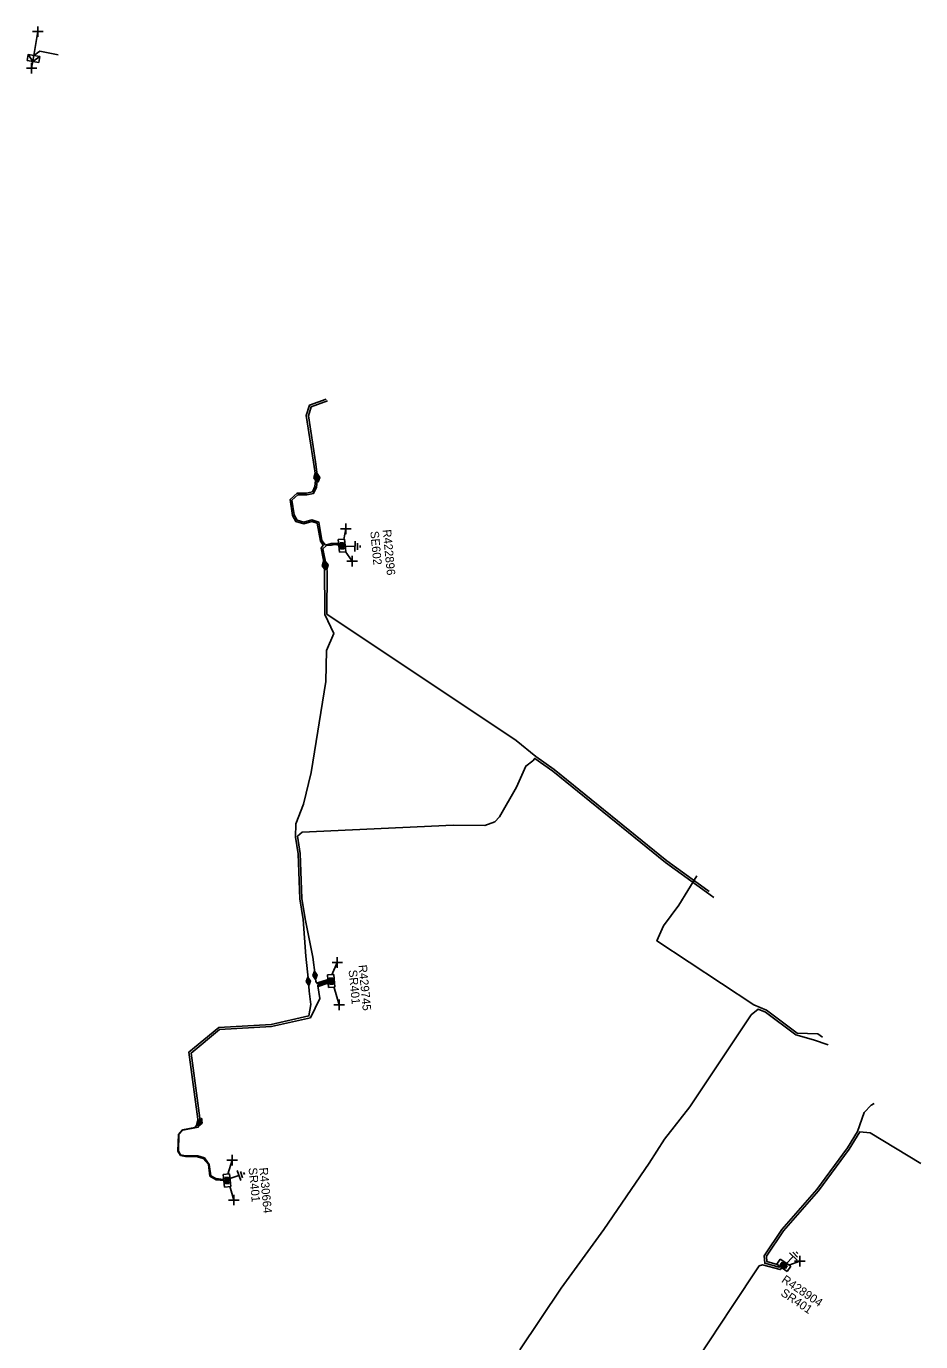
# Model space of a CAD drawing. Extents: x -540247 to -537390, y -1183887 to -1180355.
# Drawn here: x -538959.8 to -538854.3, y -1181292.1 to -1181136.9 of the extents above; entities that cross this region are included whole.
import ezdxf

# ---------------------------------------------------------------- set-up
doc = ezdxf.new("R2010")
doc.units = 0
for name, color, linetype in [('Vrstva 1', 7, 'Continuous'), ('Vrstva 14', 7, 'Continuous'), ('Vrstva 15', 7, 'Continuous'), ('Vrstva 19', 7, 'Continuous'), ('Vrstva 20', 7, 'Continuous'), ('Vrstva 28', 7, 'Continuous'), ('Vrstva 29', 7, 'Continuous'), ('Vrstva 30', 7, 'Continuous'), ('Vrstva 31', 7, 'Continuous'), ('Vrstva 34', 7, 'Continuous'), ('Vrstva 4', 7, 'Continuous'), ('Vrstva 5', 7, 'Continuous'), ('Vrstva 52', 7, 'Continuous'), ('Vrstva 59', 7, 'Continuous'), ('Vrstva 8', 7, 'Continuous'), ('Vrstva 9', 7, 'Continuous')]:
    doc.layers.add(name, color=color, linetype=linetype)

# ---------------------------------------------------------------- blocks, each defined once
blk = doc.blocks.new('NN870')
at = {"layer": 'Vrstva 4'}
for points in [[(0, -0.25), (0.5, 0), (0, 0.25), (-0.5, 0), (0, -0.25)], [(0.37, 0), (0, 0.19), (-0.36, 0), (0, -0.19), (0.37, 0)], [(0.24, 0), (0, 0.12), (-0.25, 0), (0, -0.12), (0.24, 0)], [(0.12, 0), (0, 0.06), (-0.13, 0), (0, -0.06), (0.12, 0)]]:
    blk.add_lwpolyline(points, dxfattribs=at)
blk = doc.blocks.new('NN800')
at = {"layer": 'Vrstva 1'}
for points in [[(-0.44, 0.44), (0.44, -0.44)], [(-0.44, -0.44), (0.44, 0.44)]]:
    blk.add_lwpolyline(points, dxfattribs=at)
blk = doc.blocks.new('NN620')
at = {"layer": 'Vrstva 8'}
for points in [[(0.75, 0), (-0.75, 0)], [(-0.75, 0), (-0.75, -0.75)], [(0.75, -0.75), (0.75, 0)], [(-0.75, -0.75), (0.75, -0.75)], [(0.37, -0.18), (-0.38, -0.18)], [(-0.38, -0.18), (-0.38, -0.56)], [(-0.38, -0.56), (0.37, -0.56)], [(0.32, -0.23), (-0.33, -0.23)], [(-0.33, -0.23), (-0.33, -0.51)], [(-0.33, -0.51), (0.32, -0.51)], [(0.27, -0.27), (-0.28, -0.27)], [(-0.28, -0.27), (-0.28, -0.46)], [(-0.28, -0.46), (0.27, -0.46)], [(0.23, -0.32), (-0.23, -0.32)], [(-0.23, -0.32), (-0.23, -0.42)], [(-0.23, -0.42), (0.23, -0.42)], [(-0.19, -0.37), (0.19, -0.37)], [(0.23, -0.42), (0.23, -0.32)], [(0.27, -0.46), (0.27, -0.27)], [(0.32, -0.51), (0.32, -0.23)], [(0.37, -0.56), (0.37, -0.18)]]:
    blk.add_lwpolyline(points, dxfattribs=at)
blk = doc.blocks.new('NN630')
at = {"layer": 'Vrstva 9'}
for points in [[(0, -0.7), (-0.7, 0)], [(-0.7, -0.7), (-0.7, 0), (0.7, 0), (0.7, -0.7)], [(-0.7, -0.7), (0.7, -0.7)], [(0, -0.7), (0.7, 0)]]:
    blk.add_lwpolyline(points, dxfattribs=at)
blk = doc.blocks.new('NN810')
at = {"layer": 'Vrstva 14'}
for points in [[(0, -0.64), (0, -1.89)], [(0.63, -1.89), (-0.62, -1.89)], [(0.39, -2.2), (-0.4, -2.2)], [(0, -2.52), (-0.12, -2.52)], [(0.14, -2.52), (0, -2.52)]]:
    blk.add_lwpolyline(points, dxfattribs=at)

msp = doc.modelspace()

# ---------------------------------------------------------------- linework, layer by layer
at = {"layer": 'Vrstva 20'}
for points in [[(-538924.3, -1181249.38), (-538924.25, -1181249.52), (-538925.39, -1181249.92), (-538925.44, -1181249.77)], [(-538924.28, -1181249.65), (-538924.23, -1181249.79), (-538925.37, -1181250.18), (-538925.42, -1181250.03)]]:
    msp.add_lwpolyline(points, close=True, dxfattribs=at)
at = {"layer": 'Vrstva 5'}
for points in [[(-538925.64, -1181190.12), (-538925.92, -1181188.3), (-538926.79, -1181182.81), (-538926.41, -1181181.59), (-538924.44, -1181180.87)], [(-538925.44, -1181190.14), (-538925.68, -1181188.26), (-538926.53, -1181182.83), (-538926.21, -1181181.79), (-538924.28, -1181181.08)], [(-538924.64, -1181200.51), (-538925.04, -1181198.47), (-538924.78, -1181198.1), (-538925.12, -1181197.63), (-538925.49, -1181195.53), (-538926.13, -1181195.32), (-538927.07, -1181195.59), (-538928, -1181195.33), (-538928.39, -1181194.6), (-538928.68, -1181192.72), (-538927.87, -1181191.97), (-538926.74, -1181191.97), (-538926.05, -1181191.83), (-538925.76, -1181191.2), (-538925.64, -1181190.12)], [(-538922.95, -1181197.92), (-538923.84, -1181197.9), (-538924.5, -1181198.12), (-538924.93, -1181197.55), (-538925.31, -1181195.38), (-538926.13, -1181195.11), (-538927.07, -1181195.38), (-538927.86, -1181195.16), (-538928.2, -1181194.53), (-538928.47, -1181192.78), (-538927.79, -1181192.17), (-538926.72, -1181192.17), (-538925.91, -1181192), (-538925.56, -1181191.25), (-538925.44, -1181190.14)], [(-538924.44, -1181200.47), (-538924.82, -1181198.54), (-538924.4, -1181198.15), (-538923.81, -1181198.12), (-538923.39, -1181198.02), (-538922.93, -1181198.09)], [(-538939.42, -1181266.19), (-538939.57, -1181265.82), (-538940.62, -1181257.93), (-538937.1, -1181255.02), (-538930.93, -1181254.65), (-538926.47, -1181253.65), (-538926.26, -1181252.31), (-538926.42, -1181250.75), (-538926.53, -1181249.57), (-538926.85, -1181246.62), (-538927.16, -1181242.28), (-538927.54, -1181239.82), (-538927.73, -1181234.52), (-538928.06, -1181232.56), (-538928.03, -1181231), (-538927.09, -1181228.68), (-538926.19, -1181224.92), (-538924.47, -1181214.19), (-538924.38, -1181210.54), (-538923.53, -1181208.54), (-538924.59, -1181206.29), (-538924.64, -1181200.51)], [(-538879.24, -1181238.98), (-538879.42, -1181238.86), (-538884.23, -1181235.37), (-538897.55, -1181224.59), (-538899.71, -1181223.05), (-538902, -1181221.17), (-538924.34, -1181206.25), (-538924.31, -1181201.17), (-538924.44, -1181200.47)], [(-538924.22, -1181249.44), (-538925.44, -1181249.86), (-538925.65, -1181249.59), (-538925.74, -1181248.86), (-538926.01, -1181246.73), (-538926.92, -1181242.18), (-538927.29, -1181239.8), (-538927.48, -1181234.5), (-538927.83, -1181232.46), (-538927.27, -1181231.99), (-538909.45, -1181231.13), (-538905.71, -1181231.19), (-538904.55, -1181230.75), (-538904, -1181230.17), (-538901.99, -1181226.68), (-538900.87, -1181224.17), (-538900.04, -1181223.54), (-538899.83, -1181223.27), (-538897.71, -1181224.79), (-538884.39, -1181235.57), (-538879.56, -1181239.06), (-538878.7, -1181239.68)], [(-538880.69, -1181237.12), (-538882.82, -1181240.59), (-538884.62, -1181243.02), (-538885.42, -1181244.81), (-538873.96, -1181252.35), (-538872.48, -1181252.99), (-538868.88, -1181255.67), (-538866.43, -1181255.78), (-538865.86, -1181256.18)], [(-538939.31, -1181266.21), (-538939.33, -1181265.72), (-538940.36, -1181258.03), (-538937, -1181255.26), (-538930.89, -1181254.89), (-538926.29, -1181253.87), (-538925.19, -1181251.6), (-538925.43, -1181250.12), (-538924.2, -1181249.69)], [(-538901.59, -1181293.05), (-538896.72, -1181285.79), (-538891.67, -1181278.85), (-538886.31, -1181271.02), (-538884.5, -1181268.2), (-538881.53, -1181264.39), (-538874.28, -1181253.53), (-538873.47, -1181252.84), (-538872.6, -1181253.21), (-538869.03, -1181255.87), (-538866.95, -1181256.49), (-538865.19, -1181257.05)], [(-538870.88, -1181283.21), (-538870.98, -1181283.3), (-538872.7, -1181282.84), (-538872.75, -1181281.95), (-538870.67, -1181278.84), (-538866.56, -1181274.12), (-538862.94, -1181269.23), (-538861.73, -1181267.28), (-538860.97, -1181265.07), (-538860.14, -1181264.17), (-538859.79, -1181263.99)], [(-538936.5, -1181273.06), (-538937.42, -1181272.98), (-538938.15, -1181272.56), (-538938.32, -1181271.17), (-538938.93, -1181270.46), (-538939.6, -1181270.3), (-538941.02, -1181270.23), (-538941.6, -1181270.12), (-538941.92, -1181269.63), (-538941.87, -1181267.66), (-538941.4, -1181267.1), (-538939.91, -1181266.81), (-538939.42, -1181266.19)], [(-538936.53, -1181272.96), (-538937.45, -1181272.84), (-538938.05, -1181272.54), (-538938.24, -1181271.18), (-538938.79, -1181270.4), (-538939.59, -1181270.18), (-538941.01, -1181270.17), (-538941.61, -1181270.03), (-538941.85, -1181269.63), (-538941.82, -1181267.66), (-538941.36, -1181267.13), (-538939.53, -1181266.78), (-538939.31, -1181266.21)], [(-538871.24, -1181282.97), (-538872.44, -1181282.65), (-538872.49, -1181282.01), (-538870.47, -1181279), (-538866.36, -1181274.28), (-538862.74, -1181269.37), (-538861.48, -1181267.34), (-538860.24, -1181267.44), (-538854.29, -1181271.06)], [(-538870.65, -1181283.38), (-538870.86, -1181283.58), (-538872.97, -1181283.03), (-538873.33, -1181283.15), (-538876.6, -1181288.05), (-538880.49, -1181293.95)]]:
    msp.add_lwpolyline(points, dxfattribs=at)
at = {"layer": 'Vrstva 52'}
msp.add_lwpolyline([(-538956.03, -1181140.26), (-538958.22, -1181139.82), (-538958.91, -1181140.34)], dxfattribs=at)
at = {"layer": 'Vrstva 59'}
for points in [[(-538958.91, -1181140.34), (-538958.44, -1181137.51)], [(-538958.91, -1181140.34), (-538959.18, -1181141.83)], [(-538922.35, -1181197.44), (-538922.12, -1181196.17)], [(-538922.21, -1181198.8), (-538921.36, -1181200)], [(-538923.78, -1181248.79), (-538923.12, -1181247.36)], [(-538923.52, -1181250.19), (-538922.89, -1181252.35)], [(-538936.05, -1181272.34), (-538935.53, -1181270.67)], [(-538935.8, -1181273.76), (-538935.33, -1181275.38)], [(-538869.83, -1181283.06), (-538868.56, -1181282.6)]]:
    msp.add_lwpolyline(points, dxfattribs=at)

# ---------------------------------------------------------------- block references
at = {"layer": 'Vrstva 15'}
for p, rotation in [((-538922.93, -1181198.2), 88.37947224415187), ((-538936.5, -1181273.1), 109.31079166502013), ((-538870.66, -1181283.38), 135)]:
    msp.add_blockref('NN810', p, dxfattribs=dict(at, rotation=rotation))
at = {"layer": 'Vrstva 19'}
for p, rotation in [((-538925.64, -1181190.12), -81.14044727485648), ((-538925.44, -1181190.14), -82.8374361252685), ((-538924.64, -1181200.51), -78.90627776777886), ((-538924.44, -1181200.47), -79.49968060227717), ((-538925.74, -1181248.86), -82.84044165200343), ((-538926.53, -1181249.57), -82.14801666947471), ((-538939.42, -1181266.19), 51.67988613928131), ((-538939.31, -1181266.21), 68.89516112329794)]:
    msp.add_blockref('NN870', p, dxfattribs=dict(at, rotation=rotation))
at = {"layer": 'Vrstva 28'}
for p, rotation in [((-538922.93, -1181198.2), 95.45934167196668), ((-538924.21, -1181249.57), 95.45934167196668), ((-538936.5, -1181273.1), 95.45934167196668), ((-538870.66, -1181283.38), 145.967763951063)]:
    msp.add_blockref('NN620', p, dxfattribs=dict(at, rotation=rotation))
at = {"layer": 'Vrstva 31', "rotation": -10.091980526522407}
msp.add_blockref('NN630', (-538958.91, -1181140.34), dxfattribs=at)
at = {"layer": 'Vrstva 34'}
for p, rotation in [((-538958.44, -1181137.51), 45), ((-538959.18, -1181141.83), 45), ((-538922.12, -1181196.17), 45.00000009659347), ((-538921.36, -1181200), 45.00000009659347), ((-538923.12, -1181247.36), 45), ((-538922.89, -1181252.35), 45), ((-538935.53, -1181270.67), 45), ((-538935.33, -1181275.38), 45), ((-538868.56, -1181282.6), 45)]:
    msp.add_blockref('NN800', p, dxfattribs=dict(at, rotation=rotation))

# ---------------------------------------------------------------- texts
at = {"layer": 'Vrstva 29'}
for s, rotation, p in [('R422896', 275.459, (-538917.77, -1181196.3)), ('R429745', 275.459, (-538920.62, -1181247.67)), ('R430664', 275.459, (-538932.32, -1181271.59)), ('R428904', 325.968, (-538870.79, -1181285))]:
    msp.add_text(s, height=1, rotation=rotation, dxfattribs=at).set_placement(p)
at = {"layer": 'Vrstva 30'}
for s, rotation, p in [('SE602', 275.459, (-538919.23, -1181196.49)), ('SR401', 275.459, (-538921.79, -1181248.26)), ('SR401', 275.459, (-538933.59, -1181271.59)), ('SR401', 325.968, (-538870.89, -1181286.57))]:
    msp.add_text(s, height=1, rotation=rotation, dxfattribs=at).set_placement(p)

doc.saveas('drawing.dxf')
